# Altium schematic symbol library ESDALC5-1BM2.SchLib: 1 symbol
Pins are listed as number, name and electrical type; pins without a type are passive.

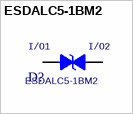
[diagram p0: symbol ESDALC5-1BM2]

## ESDALC5-1BM2
designator D?
footprint ST_SOD882TB
pins: 1 O/I1, 2 O/I2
